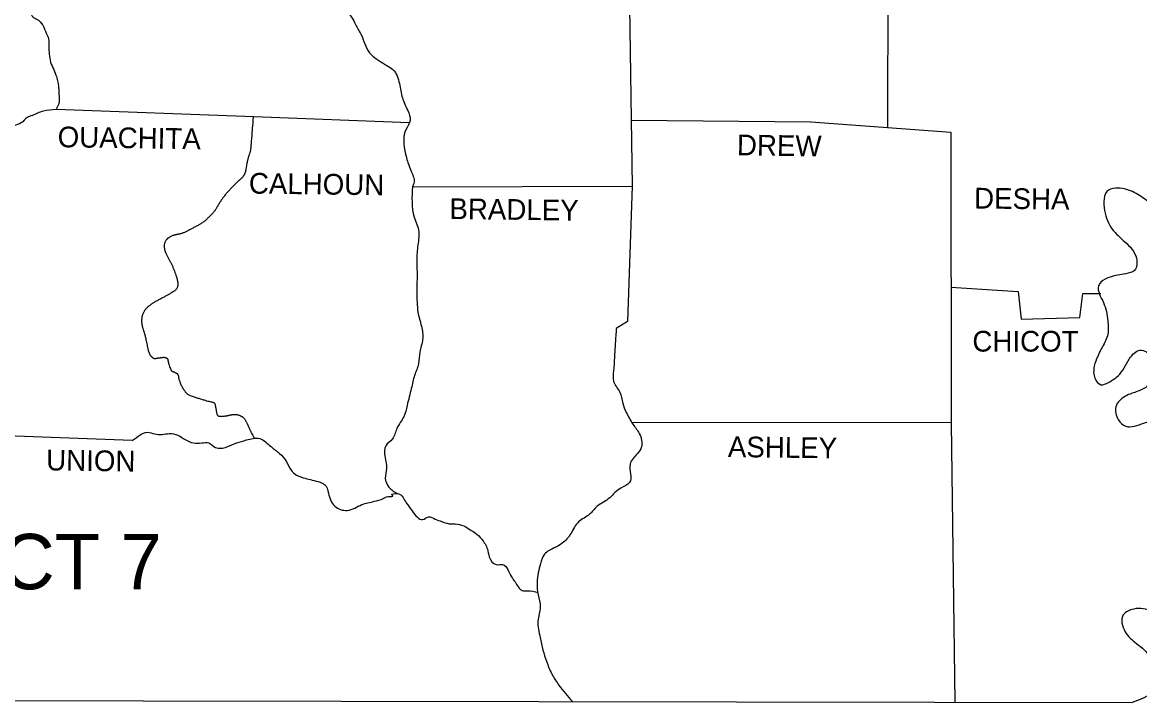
# Model space of a CAD drawing. Extents: x -0.3 to 2.65, y 0 to 1.9.
# Drawn here: x 1.1888 to 1.2937, y 0.5736 to 0.6375 of the extents above; entities that cross this region are included whole.
import ezdxf

# ---------------------------------------------------------------- set-up
doc = ezdxf.new("R2010")
doc.units = 0
doc.layers.add('Default', color=7, linetype='Continuous')

msp = doc.modelspace()

# ---------------------------------------------------------------- linework, layer by layer
at = {"layer": 'Default'}
for points in [[(1.24669, 0.6468), (1.24674, 0.64107), (1.24576, 0.64105), (1.24604, 0.62211)], [(1.27755, 0.64437), (1.27698, 0.64315), (1.27457, 0.64291), (1.27444, 0.64125), (1.27008, 0.64125), (1.27003, 0.62762)], [(1.19194, 0.62934), (1.21051, 0.62865), (1.22514, 0.62808)], [(1.24595, 0.62831), (1.26282, 0.62816), (1.27597, 0.62717)], [(1.27597, 0.62717), (1.276, 0.59986), (1.27636, 0.57365)], [(1.2254, 0.62206), (1.24604, 0.62211)], [(1.24604, 0.62211), (1.2456, 0.60941), (1.24456, 0.60876)], [(1.27598, 0.61264), (1.28232, 0.61223), (1.28258, 0.60961), (1.28811, 0.60977), (1.28837, 0.61203), (1.29007, 0.61203)], [(1.12566, 0.61083), (1.12576, 0.5739), (1.29301, 0.57362)], [(1.19908, 0.59823), (1.17962, 0.59896), (1.1795, 0.60378)], [(1.24603, 0.59991), (1.276, 0.59994)]]:
    msp.add_lwpolyline(points, dxfattribs=at)
for points in [[(1.18894, 0.64071), (1.18894, 0.63985), (1.18922, 0.63905), (1.18953, 0.63869), (1.18969, 0.63806), (1.1901, 0.6378), (1.19067, 0.63723), (1.19101, 0.63648), (1.19122, 0.63596), (1.19124, 0.63532), (1.19127, 0.63469), (1.19137, 0.63394), (1.19192, 0.63254), (1.19207, 0.632), (1.19215, 0.63153), (1.1922, 0.63075), (1.19218, 0.62984), (1.19194, 0.62934)], [(1.21707, 0.64037), (1.21811, 0.63967), (1.21897, 0.63874), (1.21962, 0.63809), (1.22006, 0.63729), (1.22057, 0.63638), (1.22138, 0.63464), (1.22205, 0.63404), (1.22301, 0.63345), (1.22358, 0.63306), (1.22418, 0.63174), (1.22447, 0.63041), (1.22496, 0.62922), (1.22519, 0.62831), (1.22478, 0.62741), (1.22467, 0.62559), (1.22498, 0.62432), (1.22532, 0.62344), (1.22555, 0.62237), (1.2254, 0.62206)], [(1.29999, 0.63653), (1.29952, 0.63547), (1.29903, 0.63366), (1.29916, 0.6321), (1.29983, 0.63075), (1.30095, 0.63005), (1.30211, 0.62901), (1.30206, 0.62738), (1.30136, 0.62678), (1.29975, 0.6272), (1.29853, 0.62777), (1.29747, 0.62743), (1.29604, 0.62676), (1.29503, 0.6266), (1.29506, 0.62445), (1.29646, 0.62287), (1.2977, 0.62287), (1.29913, 0.62271), (1.29962, 0.62105), (1.29879, 0.6197), (1.29742, 0.61898), (1.29571, 0.61981), (1.29449, 0.62069), (1.29322, 0.62152), (1.29169, 0.62193), (1.2908, 0.62175), (1.29042, 0.61983), (1.29114, 0.61809), (1.29234, 0.61688), (1.29342, 0.61535), (1.29324, 0.6142), (1.29241, 0.61389), (1.29096, 0.61358), (1.29008, 0.61309), (1.28987, 0.61275), (1.29031, 0.6112), (1.29073, 0.60948), (1.29073, 0.60821), (1.29023, 0.60702), (1.28946, 0.60521), (1.28953, 0.60404), (1.29008, 0.60347), (1.29078, 0.60368), (1.29169, 0.6043), (1.29226, 0.60505), (1.29278, 0.60593), (1.29374, 0.60671), (1.2949, 0.60604), (1.29521, 0.60463), (1.29451, 0.60339), (1.29355, 0.60285), (1.29239, 0.6024), (1.29148, 0.60139), (1.29171, 0.6002), (1.29241, 0.59958), (1.2941, 0.59986), (1.29524, 0.60036), (1.29586, 0.60103), (1.29664, 0.60181), (1.29706, 0.60256), (1.29765, 0.60339), (1.29871, 0.60362), (1.29921, 0.60292), (1.29903, 0.60139), (1.29838, 0.59994), (1.29752, 0.59867), (1.29656, 0.59781), (1.2954, 0.59595), (1.29563, 0.59421), (1.29604, 0.59278), (1.29669, 0.59169), (1.29778, 0.59193), (1.29903, 0.59208), (1.29978, 0.59149), (1.29967, 0.59022), (1.29874, 0.58897), (1.29791, 0.5878), (1.29744, 0.58612), (1.29763, 0.58498), (1.29763, 0.58394), (1.29724, 0.5828), (1.29659, 0.58215), (1.29493, 0.58223), (1.29316, 0.58241), (1.29218, 0.58186), (1.29236, 0.58028), (1.29342, 0.57917), (1.29415, 0.57857), (1.29519, 0.57727), (1.29565, 0.57624), (1.2955, 0.57533), (1.29488, 0.57455), (1.29301, 0.57362)], [(1.18969, 0.62875), (1.18922, 0.62855), (1.18865, 0.62805), (1.18795, 0.62779), (1.18733, 0.62761), (1.18647, 0.62707), (1.18587, 0.6266), (1.18499, 0.62621), (1.18416, 0.62595), (1.18315, 0.62624), (1.18261, 0.62655), (1.18204, 0.62681), (1.18009, 0.62681)], [(1.18969, 0.62875), (1.19075, 0.62919), (1.19194, 0.62934)], [(1.2254, 0.62206), (1.22558, 0.61921), (1.226, 0.61784), (1.22589, 0.61641), (1.22581, 0.61498), (1.22584, 0.61371), (1.22581, 0.61247), (1.22584, 0.6112), (1.22592, 0.61029), (1.22625, 0.60897), (1.22636, 0.60772), (1.2261, 0.60653), (1.22597, 0.60544), (1.22561, 0.60435), (1.2253, 0.60313), (1.22491, 0.60152), (1.22459, 0.60046), (1.22395, 0.59937), (1.22353, 0.59838), (1.22291, 0.59774), (1.22283, 0.59665), (1.22296, 0.59561), (1.22286, 0.5947), (1.22319, 0.59385), (1.224, 0.59325)], [(1.24456, 0.60876), (1.24446, 0.60736), (1.24438, 0.60604), (1.2443, 0.60476), (1.2443, 0.60378), (1.24488, 0.60277), (1.24516, 0.60173), (1.2455, 0.60087), (1.24612, 0.59976), (1.24672, 0.59888), (1.24692, 0.59763), (1.24654, 0.59701), (1.24586, 0.59602), (1.24581, 0.59429), (1.24498, 0.59377), (1.24394, 0.59286), (1.24337, 0.59245), (1.24272, 0.59203), (1.24205, 0.5913), (1.24101, 0.5906), (1.24029, 0.58949), (1.23948, 0.58858), (1.23878, 0.58817), (1.23782, 0.58757), (1.23743, 0.58666), (1.23712, 0.58495), (1.23722, 0.58373), (1.23741, 0.58262), (1.2372, 0.58127), (1.23741, 0.57974), (1.23767, 0.57855), (1.238, 0.57751), (1.2385, 0.57631), (1.23917, 0.57525), (1.24043, 0.57371)], [(1.19908, 0.59823), (1.19983, 0.59875), (1.2005, 0.59901), (1.2012, 0.59885), (1.2019, 0.5988), (1.20255, 0.59888), (1.20338, 0.59872), (1.20405, 0.59833), (1.20483, 0.598), (1.20561, 0.598), (1.20629, 0.598), (1.20691, 0.59758), (1.20797, 0.59763), (1.2089, 0.598), (1.20981, 0.59828), (1.21106, 0.59841), (1.21212, 0.59766), (1.21292, 0.59701), (1.21355, 0.59628), (1.21401, 0.59545), (1.21453, 0.59499), (1.21534, 0.59468), (1.21598, 0.59452), (1.21674, 0.59431), (1.21715, 0.59411), (1.21751, 0.59328), (1.21811, 0.59206), (1.21928, 0.59167), (1.22065, 0.59221), (1.22182, 0.59252), (1.22265, 0.59278), (1.22312, 0.59296), (1.22358, 0.59304), (1.22348, 0.59312), (1.224, 0.59325), (1.22452, 0.59289), (1.22483, 0.59239), (1.22537, 0.59164), (1.22587, 0.59102), (1.22636, 0.59081), (1.2269, 0.59107), (1.22755, 0.59084), (1.22815, 0.59063), (1.22885, 0.59042), (1.22942, 0.5904), (1.23022, 0.59022), (1.23079, 0.58988), (1.23134, 0.58954), (1.23191, 0.58897), (1.23245, 0.58804), (1.23263, 0.58731), (1.23326, 0.58658), (1.23388, 0.58658), (1.23471, 0.58542), (1.23505, 0.58495), (1.23572, 0.58415), (1.23621, 0.58412), (1.2372, 0.58397)]]:
    msp.add_spline(points, degree=3, dxfattribs=at)
msp.add_open_spline([(1.21045, 0.62865), (1.21038, 0.62772), (1.2103, 0.62678), (1.21023, 0.62585), (1.21021, 0.62561), (1.21015, 0.62538), (1.21009, 0.62514), (1.21005, 0.62503), (1.21002, 0.62491), (1.20998, 0.6248), (1.20995, 0.62468), (1.20992, 0.62457), (1.20989, 0.62445), (1.20984, 0.62423), (1.20982, 0.62401), (1.20978, 0.62379), (1.20976, 0.62368), (1.20974, 0.62357), (1.20971, 0.62346), (1.20969, 0.62341), (1.20967, 0.62336), (1.20965, 0.62331), (1.20964, 0.62328), (1.20963, 0.62325), (1.20962, 0.62323), (1.20961, 0.6232), (1.20959, 0.62318), (1.20958, 0.62315), (1.20954, 0.62308), (1.20949, 0.62301), (1.20943, 0.62294), (1.20937, 0.62288), (1.20931, 0.62282), (1.20925, 0.62277), (1.20919, 0.62271), (1.20912, 0.62266), (1.20906, 0.6226), (1.209, 0.62254), (1.20894, 0.62249), (1.20888, 0.62243), (1.20876, 0.6223), (1.20864, 0.62218), (1.20852, 0.62205), (1.20839, 0.62192), (1.20827, 0.6218), (1.20815, 0.62167), (1.20791, 0.62143), (1.20771, 0.62115), (1.2075, 0.62087), (1.20745, 0.62079), (1.20739, 0.62071), (1.20734, 0.62063), (1.20729, 0.62054), (1.20724, 0.62046), (1.20719, 0.62038), (1.20714, 0.62029), (1.20709, 0.62021), (1.20704, 0.62013), (1.20699, 0.62004), (1.20694, 0.61996), (1.20688, 0.61988), (1.20671, 0.61964), (1.2065, 0.61942), (1.20629, 0.61921), (1.20605, 0.61898), (1.20581, 0.61876), (1.20553, 0.61859), (1.20527, 0.61843), (1.205, 0.61829), (1.20473, 0.61815), (1.20445, 0.618), (1.20418, 0.61786), (1.2039, 0.61773), (1.20382, 0.6177), (1.20374, 0.61767), (1.20366, 0.61765), (1.20358, 0.61763), (1.2035, 0.61761), (1.20341, 0.61759), (1.20333, 0.61758), (1.20325, 0.61756), (1.20316, 0.61754), (1.20308, 0.61753), (1.203, 0.6175), (1.20291, 0.61747), (1.20278, 0.61743), (1.20266, 0.61737), (1.20254, 0.61729), (1.20248, 0.61726), (1.20243, 0.61722), (1.20238, 0.61717), (1.20236, 0.61714), (1.20233, 0.61712), (1.20231, 0.61709), (1.20228, 0.61706), (1.20226, 0.61704), (1.20224, 0.61701), (1.20218, 0.61692), (1.20215, 0.61683), (1.20212, 0.61674), (1.20209, 0.61664), (1.20208, 0.61654), (1.20208, 0.61645), (1.2021, 0.61626), (1.20214, 0.61607), (1.20221, 0.61589), (1.20227, 0.61576), (1.20233, 0.61563), (1.20239, 0.61551), (1.20246, 0.61538), (1.20253, 0.61526), (1.20259, 0.61513), (1.20266, 0.615), (1.20273, 0.61488), (1.20279, 0.61475), (1.20286, 0.61462), (1.20291, 0.61449), (1.20297, 0.61436), (1.20306, 0.61412), (1.20314, 0.61388), (1.20322, 0.61363), (1.20325, 0.61356), (1.20327, 0.61349), (1.20329, 0.61341), (1.20331, 0.61334), (1.20333, 0.61326), (1.20334, 0.61318), (1.20336, 0.61311), (1.20337, 0.61303), (1.20337, 0.61295), (1.20337, 0.61291), (1.20337, 0.61288), (1.20337, 0.61284), (1.20337, 0.6128), (1.20336, 0.61276), (1.20335, 0.61273), (1.20334, 0.61263), (1.20329, 0.61253), (1.20323, 0.61245), (1.20316, 0.61236), (1.20308, 0.61229), (1.20299, 0.61223), (1.20276, 0.61209), (1.20253, 0.61195), (1.20229, 0.61182), (1.202, 0.61166), (1.2017, 0.61151), (1.20141, 0.61135), (1.20115, 0.61121), (1.2009, 0.61104), (1.20066, 0.61086), (1.20053, 0.61076), (1.20042, 0.61065), (1.20032, 0.61052), (1.20027, 0.61046), (1.20023, 0.6104), (1.20019, 0.61033), (1.20015, 0.61026), (1.20012, 0.61018), (1.20009, 0.61011), (1.20002, 0.60993), (1.19998, 0.60975), (1.19997, 0.60957), (1.19996, 0.6094), (1.19997, 0.60922), (1.20001, 0.60904), (1.20003, 0.60894), (1.20006, 0.60884), (1.20009, 0.60874), (1.20012, 0.60864), (1.20015, 0.60854), (1.20018, 0.60843), (1.20021, 0.60833), (1.20024, 0.60823), (1.20027, 0.60813), (1.2003, 0.60803), (1.20032, 0.60793), (1.20035, 0.60782), (1.2004, 0.60758), (1.20045, 0.60732), (1.2005, 0.60707), (1.20053, 0.60697), (1.20055, 0.60686), (1.20058, 0.60675), (1.2006, 0.60664), (1.20064, 0.60654), (1.20068, 0.60643), (1.20072, 0.60633), (1.20077, 0.60624), (1.20084, 0.60616), (1.20088, 0.60611), (1.20091, 0.60608), (1.20096, 0.60604), (1.20098, 0.60603), (1.201, 0.60601), (1.20102, 0.606), (1.20105, 0.60598), (1.20107, 0.60597), (1.2011, 0.60596), (1.20113, 0.60594), (1.20117, 0.60593), (1.20121, 0.60593), (1.20125, 0.60593), (1.20128, 0.60594), (1.20132, 0.60595), (1.20136, 0.60595), (1.20139, 0.60596), (1.20143, 0.60597), (1.20147, 0.60598), (1.2015, 0.60598), (1.20154, 0.60598), (1.20157, 0.60599), (1.20161, 0.60599), (1.20164, 0.60599), (1.20168, 0.606), (1.20171, 0.606), (1.20175, 0.60601), (1.20182, 0.60602), (1.20189, 0.60603), (1.20195, 0.60604), (1.20202, 0.60605), (1.20209, 0.60605), (1.20216, 0.60603), (1.2022, 0.60603), (1.20223, 0.60602), (1.20227, 0.606), (1.20228, 0.60599), (1.2023, 0.60598), (1.20232, 0.60597), (1.20234, 0.60596), (1.20235, 0.60595), (1.20237, 0.60593), (1.2024, 0.6059), (1.20242, 0.60586), (1.20243, 0.60582), (1.20244, 0.60578), (1.20244, 0.60574), (1.20245, 0.6057), (1.20246, 0.60563), (1.20248, 0.60556), (1.2025, 0.60549), (1.20255, 0.60529), (1.20262, 0.60509), (1.20271, 0.60489), (1.20273, 0.60483), (1.20278, 0.60477), (1.20284, 0.60474), (1.20291, 0.60471), (1.20298, 0.60468), (1.20304, 0.60465), (1.20311, 0.60461), (1.20318, 0.60458), (1.20324, 0.60455), (1.2033, 0.60452), (1.20335, 0.60446), (1.20338, 0.6044), (1.2034, 0.60436), (1.20341, 0.60433), (1.20342, 0.60429), (1.20342, 0.60425), (1.20343, 0.60421), (1.20343, 0.60417), (1.20344, 0.60413), (1.20345, 0.60409), (1.20345, 0.60405), (1.20346, 0.60401), (1.20347, 0.60397), (1.20348, 0.60393), (1.20354, 0.60378), (1.2036, 0.60363), (1.20366, 0.60349), (1.20373, 0.60333), (1.20381, 0.60319), (1.2039, 0.60305), (1.20406, 0.6028), (1.20427, 0.60257), (1.20455, 0.60246), (1.20472, 0.60238), (1.20489, 0.60233), (1.20507, 0.60227), (1.20541, 0.60217), (1.20576, 0.60206), (1.2061, 0.60196), (1.20628, 0.60191), (1.20647, 0.60188), (1.20665, 0.60183), (1.20668, 0.60183), (1.2067, 0.60182), (1.20673, 0.6018), (1.2068, 0.60174), (1.20686, 0.60166), (1.20688, 0.60158), (1.2069, 0.60143), (1.20693, 0.60128), (1.20696, 0.60114), (1.20698, 0.601), (1.20701, 0.60086), (1.20704, 0.60072), (1.20705, 0.60066), (1.20708, 0.60062), (1.20713, 0.60057), (1.20717, 0.60054), (1.20722, 0.60052), (1.20727, 0.60051), (1.20739, 0.6005), (1.20751, 0.6005), (1.20763, 0.60052), (1.20775, 0.60053), (1.20788, 0.60054), (1.208, 0.60056), (1.20808, 0.60058), (1.20817, 0.6006), (1.20826, 0.60062), (1.20834, 0.60064), (1.20843, 0.60065), (1.20852, 0.60067), (1.20867, 0.60069), (1.20883, 0.60068), (1.20899, 0.60065), (1.20907, 0.60063), (1.20914, 0.60061), (1.20922, 0.60057), (1.20926, 0.60055), (1.2093, 0.60053), (1.20933, 0.60051), (1.20937, 0.60049), (1.20941, 0.60046), (1.20945, 0.60043), (1.20954, 0.60036), (1.20962, 0.60028), (1.20968, 0.60018), (1.20974, 0.60008), (1.20979, 0.59999), (1.20984, 0.59989), (1.20988, 0.59981), (1.20992, 0.59974), (1.20995, 0.59966), (1.20999, 0.59958), (1.21002, 0.5995), (1.21006, 0.59942), (1.21009, 0.59934), (1.21013, 0.59927), (1.21016, 0.59919), (1.2102, 0.59911), (1.21024, 0.59903), (1.21028, 0.59896), (1.21037, 0.59879), (1.21044, 0.59862), (1.21056, 0.59848)], degree=3, dxfattribs=at)

# ---------------------------------------------------------------- texts
for s, rotation, p in [('OUACHITA', 359.2027, (1.19207, 0.62577)), ('DREW', 359.1352, (1.25588, 0.62502)), ('CALHOUN', 359.2686, (1.21003, 0.62142)), ('DESHA', 359.2949, (1.27816, 0.62002)), ('BRADLEY', 359.2655, (1.22887, 0.61903)), ('ASHLEY', 359.2711, (1.25503, 0.59668)), ('UNION', 359.2015, (1.19099, 0.59543))]:
    msp.add_text(s, height=0.001945, rotation=rotation, dxfattribs=at).set_placement(p)
for s, height, p in [('CHICOT', 0.001945, (1.27801, 0.60658)), ('DISTRICT 7', 0.005203, (1.16397, 0.58426))]:
    msp.add_text(s, height=height, dxfattribs=at).set_placement(p)

doc.saveas('drawing.dxf')
